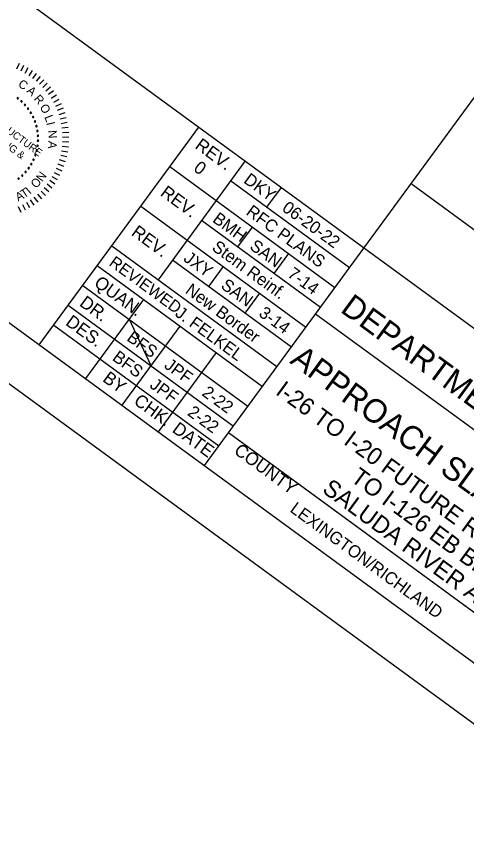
# Model space of a CAD drawing. Extents: x 1970654 to 1970899, y 796145 to 796378.
# Drawn here: x 1970821.89 to 1970840.2, y 796145.21 to 796179.11 of the extents above; entities that cross this region are included whole.
import ezdxf

# ---------------------------------------------------------------- set-up
doc = ezdxf.new("R2010")
doc.units = 0
for name, color, linetype in [('BR_BORDER LINES', 7, 'Continuous'), ('BR_TEXT', 7, 'Continuous'), ('Level 31', 7, 'Continuous')]:
    doc.layers.add(name, color=color, linetype=linetype)

msp = doc.modelspace()

# ---------------------------------------------------------------- linework, layer by layer
at = {"layer": 'BR_BORDER LINES'}
for p, q in [((1970738.359, 796227.562), (1970847.014, 796148.01)), ((1970811.99, 796187.287), (1970829.306, 796174.609)), ((1970829.532, 796160.81), (1970842, 796177.84)), ((1970822.808, 796165.733), (1970829.306, 796174.609)), ((1970829.306, 796174.609), (1970853.513, 796156.886)), ((1970831.189, 796173.23), (1970827.644, 796168.389)), ((1970828.124, 796172.995), (1970834.848, 796168.072)), ((1970830.598, 796172.424), (1970835.439, 796168.879)), ((1970837.949, 796172.305), (1970855.431, 796159.506)), ((1970832.077, 796171.341), (1970832.668, 796172.147)), ((1970826.943, 796171.381), (1970833.667, 796166.458)), ((1970829.416, 796170.81), (1970834.258, 796167.265)), ((1970830.896, 796169.727), (1970831.486, 796170.534)), ((1970825.761, 796169.768), (1970832.485, 796164.845)), ((1970828.235, 796169.196), (1970833.076, 796165.651)), ((1970832.375, 796168.644), (1970832.966, 796169.451)), ((1970825.171, 796168.961), (1970831.895, 796164.038)), ((1970829.714, 796168.113), (1970830.305, 796168.92)), ((1970824.58, 796168.154), (1970831.304, 796163.231)), ((1970831.193, 796167.03), (1970831.784, 796167.837)), ((1970827.053, 796167.582), (1970824.69, 796164.355)), ((1970823.989, 796167.347), (1970830.713, 796162.424)), ((1970834.061, 796166.996), (1970834.061, 796166.996)), ((1970834.061, 796166.996), (1970851.544, 796154.196)), ((1970823.398, 796166.54), (1970830.122, 796161.617)), ((1970828.533, 796166.499), (1970826.17, 796163.272)), ((1970830.012, 796165.416), (1970827.649, 796162.189)), ((1970830.516, 796162.155), (1970847.999, 796149.355)), ((1970830.831, 796161.924), (1970847.999, 796149.355))]:
    msp.add_line(p, q, dxfattribs=at)
at = {"layer": 'BR_TEXT'}
for p, q in [((1970821.985, 796177.196), (1970821.887, 796176.961)), ((1970822.169, 796177.112), (1970822.056, 796176.884)), ((1970822.347, 796177.017), (1970822.221, 796176.796)), ((1970822.519, 796176.912), (1970822.38, 796176.699)), ((1970822.685, 796176.796), (1970822.533, 796176.592)), ((1970822.843, 796176.67), (1970822.678, 796176.476)), ((1970822.993, 796176.535), (1970822.817, 796176.351)), ((1970823.134, 796176.391), (1970822.948, 796176.218)), ((1970823.267, 796176.239), (1970823.07, 796176.077)), ((1970823.39, 796176.079), (1970823.183, 796175.929)), ((1970823.503, 796175.911), (1970823.288, 796175.775)), ((1970823.606, 796175.737), (1970823.382, 796175.614)), ((1970823.697, 796175.557), (1970823.467, 796175.448)), ((1970823.778, 796175.372), (1970823.542, 796175.277)), ((1970823.847, 796175.183), (1970823.605, 796175.102)), ((1970823.905, 796174.989), (1970823.659, 796174.924)), ((1970823.95, 796174.792), (1970823.701, 796174.742)), ((1970823.984, 796174.593), (1970823.732, 796174.558)), ((1970824.005, 796174.392), (1970823.751, 796174.373)), ((1970824.011, 796173.989), (1970823.756, 796174)), ((1970824.014, 796174.191), (1970823.76, 796174.187)), ((1970823.968, 796173.587), (1970823.716, 796173.63)), ((1970823.995, 796173.787), (1970823.742, 796173.814)), ((1970823.876, 796173.194), (1970823.632, 796173.267)), ((1970823.928, 796173.389), (1970823.68, 796173.447)), ((1970823.737, 796172.815), (1970823.503, 796172.917)), ((1970823.812, 796173.003), (1970823.573, 796173.09)), ((1970823.552, 796172.456), (1970823.333, 796172.586)), ((1970823.65, 796172.633), (1970823.423, 796172.749)), ((1970823.326, 796172.122), (1970823.124, 796172.277)), ((1970823.444, 796172.286), (1970823.233, 796172.428)), ((1970823.06, 796171.818), (1970822.879, 796171.997)), ((1970823.198, 796171.966), (1970823.006, 796172.133)), ((1970822.598, 796171.428), (1970822.452, 796171.637)), ((1970822.76, 796171.548), (1970822.601, 796171.748)), ((1970822.914, 796171.679), (1970822.744, 796171.868)), ((1970822.072, 796171.128), (1970821.967, 796171.36)), ((1970822.253, 796171.217), (1970822.134, 796171.442)), ((1970822.429, 796171.317), (1970822.296, 796171.535))]:
    msp.add_line(p, q, dxfattribs=at)
for centre, start, end in [((1970821.93, 796175.781), 143.3174, 323.3174), ((1970821.93, 796175.781), 323.3174, 143.3174), ((1970822.084, 796175.654), 137.779, 317.779), ((1970822.084, 796175.654), 317.779, 137.779), ((1970822.224, 796175.513), 132.2405, 312.2405), ((1970822.224, 796175.513), 312.2405, 132.2405), ((1970822.351, 796175.359), 126.702, 306.702), ((1970822.351, 796175.359), 306.702, 126.702), ((1970822.462, 796175.193), 121.1636, 301.1636), ((1970822.462, 796175.193), 301.1636, 121.1636), ((1970822.556, 796175.018), 115.6251, 295.6251), ((1970822.556, 796175.018), 295.6251, 115.6251), ((1970822.633, 796174.834), 110.0866, 290.0866), ((1970822.633, 796174.834), 290.0866, 110.0866), ((1970822.692, 796174.644), 104.5482, 284.5482), ((1970822.692, 796174.644), 284.5482, 104.5482), ((1970822.732, 796174.449), 99.0097, 279.0097), ((1970822.754, 796174.25), 93.4713, 273.4713), ((1970822.732, 796174.449), 279.0097, 99.0097), ((1970822.754, 796174.25), 273.4713, 93.4713), ((1970822.756, 796174.051), 87.9328, 267.9328), ((1970822.756, 796174.051), 267.9328, 87.9328), ((1970822.702, 796173.656), 76.8559, 256.8559), ((1970822.702, 796173.656), 256.8559, 76.8559), ((1970822.738, 796173.852), 82.3943, 262.3943), ((1970822.738, 796173.852), 262.3943, 82.3943), ((1970822.574, 796173.279), 65.779, 245.779), ((1970822.574, 796173.279), 245.779, 65.779), ((1970822.647, 796173.465), 71.3174, 251.3174), ((1970822.647, 796173.465), 251.3174, 71.3174), ((1970822.376, 796172.934), 54.702, 234.702), ((1970822.376, 796172.934), 234.702, 54.702), ((1970822.483, 796173.102), 60.2405, 240.2405), ((1970822.483, 796173.102), 240.2405, 60.2405), ((1970822.115, 796172.633), 43.6251, 223.6251), ((1970822.115, 796172.633), 223.6251, 43.6251), ((1970822.252, 796172.778), 49.1636, 229.1636), ((1970822.252, 796172.778), 229.1636, 49.1636), ((1970821.964, 796172.503), 38.0866, 218.0866), ((1970821.964, 796172.503), 218.0866, 38.0866)]:
    msp.add_arc(centre, 0.028, start, end, dxfattribs=at)
at = {"layer": 'Level 31'}
msp.add_line((1970826.463, 796166.775), (1970827.351, 796164.885), dxfattribs=at)
msp.add_lwpolyline([(1970731.261, 796230.28), (1970847.449, 796145.214), (1970899.434, 796216.218), (1970783.245, 796301.284)], close=True, dxfattribs=at)

# ---------------------------------------------------------------- texts
at = {"layer": 'BR_TEXT'}
for s, height, rotation, p in [('C', 0.349, 328.5187, (1970821.919, 796176.278)), ('A', 0.349, 319.4887, (1970822.268, 796176.047)), ('INFRASTRUCTURE', 0.29909, 323.3174, (1970819.852, 796175.586)), ('R', 0.349, 310.4587, (1970822.564, 796175.746)), ('O', 0.349, 301.4286, (1970822.809, 796175.419)), ('CONSULTING &', 0.29909, 323.3174, (1970819.681, 796175.073)), ('L', 0.349, 290.8986, (1970823.009, 796175.022)), ('I', 0.349, 283.3686, (1970823.089, 796174.776)), ('N', 0.349, 274.3386, (1970823.166, 796174.468)), ('A', 0.349, 265.3085, (1970823.181, 796174.049)), ('REV.', 0.52, 323.7906, (1970829.114, 796173.773)), ('0', 0.52, 323.7906, (1970829.052, 796172.851)), ('N', 0.349, 52.9991, (1970822.929, 796172.355)), ('DKY', 0.5, 323.7906, (1970831.095, 796172.369)), ('O', 0.349, 46.9991, (1970822.677, 796172.086)), ('REV.', 0.52, 323.7906, (1970827.702, 796171.844)), ('A', 0.349, 27.186, (1970821.944, 796171.572)), ('T', 0.349, 33.186, (1970822.186, 796171.694)), ('I', 0.349, 41.6998, (1970822.428, 796171.851)), ('06-20-22', 0.5, 323.7906, (1970832.659, 796171.224)), ('RFC PLANS', 0.5, 323.7906, (1970831.193, 796171.07)), ('BMH', 0.5, 323.7906, (1970829.828, 796170.772)), ('REV.', 0.52, 323.7906, (1970826.52, 796170.23)), ('Stem Reinf.', 0.5, 323.7906, (1970829.8, 796169.625)), ('SAN', 0.5, 323.7906, (1970831.337, 796169.667)), ('REVIEWED', 0.48, 323.7906, (1970825.615, 796168.999)), ('JXY', 0.5, 323.7906, (1970828.647, 796169.181)), ('7-14', 0.5, 323.7906, (1970832.881, 796168.537)), ('QUAN.', 0.52, 323.7906, (1970825.003, 796168.167)), ('New Border', 0.5, 323.7906, (1970828.719, 796167.872)), ('SAN', 0.5, 323.7906, (1970830.166, 796168.069)), ('DR.', 0.52, 323.7906, (1970824.409, 796167.355)), ('DEPARTMENT  OF  TRANSPORTATION', 0.94348, 323.7906, (1970835.027, 796167.102)), ('J. FELKEL', 0.5, 323.7906, (1970828.302, 796166.938)), ('3-14', 0.5, 323.7906, (1970831.71, 796166.938)), ('DES.', 0.52, 323.7906, (1970823.842, 796166.573)), ('BFS', 0.5, 323.7906, (1970826.335, 796165.939)), ('BFS', 0.5, 323.7906, (1970825.746, 796165.135)), ('APPROACH SLAB NO. 3 DETAILS', 0.96, 323.7906, (1970832.974, 796165.014)), ('JPF', 0.5, 323.7906, (1970827.859, 796164.823)), ('BY', 0.52, 323.7906, (1970825.353, 796164.276)), ('JPF', 0.5, 323.7906, (1970827.27, 796164.019)), ('I-26 TO I-20 FUTURE RAMPS AND RAMP I-26 WB', 0.7, 323.7906, (1970832.393, 796163.747)), ('2-22', 0.5, 323.7906, (1970829.395, 796163.699)), ('CHK.', 0.52, 323.7906, (1970826.618, 796163.357)), ('2-22', 0.5, 323.7906, (1970828.807, 796162.894)), ('DATE', 0.52, 323.7906, (1970828.184, 796162.21)), ('COUNTY', 0.52, 323.7906, (1970830.697, 796161.337)), ('TO I-126 EB BRIDGE OVER', 0.7, 323.7906, (1970835.446, 796160.211)), ('SALUDA RIVER AND CSX R.R.', 0.7, 323.7906, (1970834.29, 796159.755)), ('LEXINGTON/RICHLAND', 0.49998, 323.7906, (1970832.982, 796158.959))]:
    msp.add_text(s, height=height, rotation=rotation, dxfattribs=at).set_placement(p)

doc.saveas('drawing.dxf')
